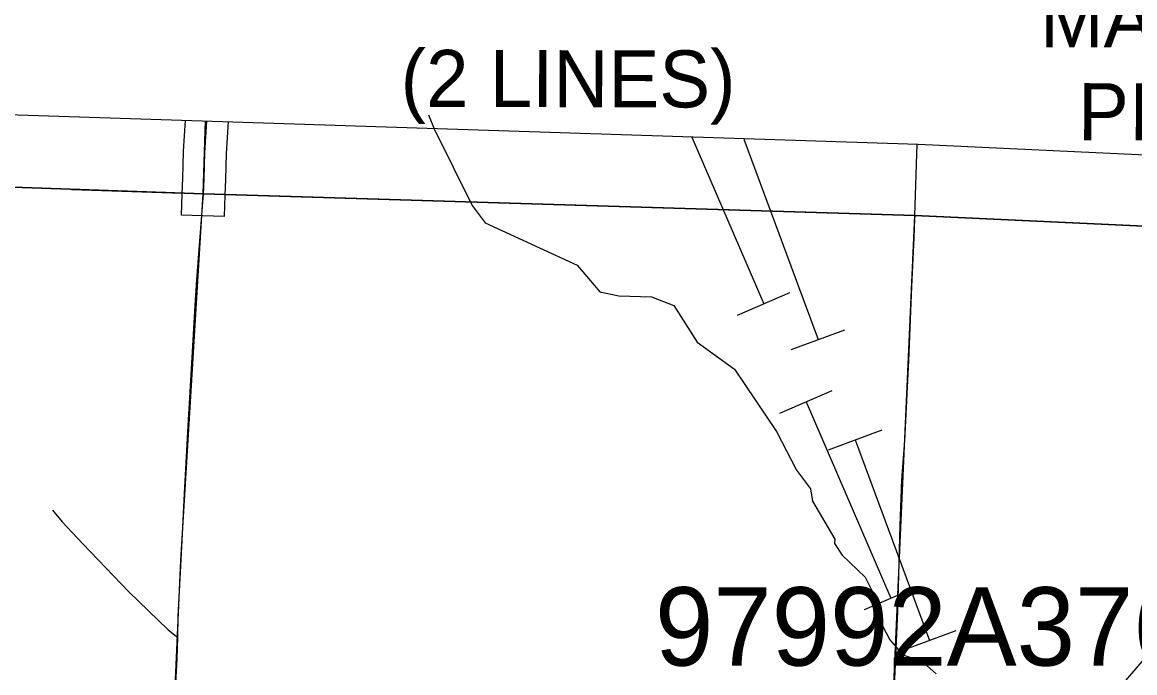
# Model space of a CAD drawing. Extents: x -157.2 to -99.3, y 12.2 to 46.2.
# Drawn here: x -146.67 to -145.11, y 40.555 to 41.468 of the extents above; entities that cross this region are included whole.
import ezdxf

# ---------------------------------------------------------------- set-up
doc = ezdxf.new("R2010")
doc.units = 0
for name, color, linetype in [('tdCoCityStreetMajor', 7, 'Continuous'), ('tdCoCityStreetMinor', 7, 'Continuous'), ('tdCoClipBndry', 7, 'Continuous'), ('tdCoCoBndry', 7, 'Continuous'), ('tdCoCoBndryPart', 7, 'Continuous'), ('tdCoCorpBndry', 7, 'Continuous'), ('tdCoHydroRiver', 7, 'Continuous'), ('tdCoPipe1', 7, 'Continuous'), ('tdCoPipe2', 7, 'Continuous'), ('tdCoPipeTxt', 7, 'Continuous'), ('tdCoSecRteBand', 7, 'Continuous'), ('tdCoSecRteCL', 7, 'Continuous'), ('tdCoSectLine', 7, 'Continuous'), ('tdCoSectLinePart', 7, 'Continuous'), ('tdCoStrucPriMaintName', 7, 'Continuous'), ('tdCoSurfGravel', 7, 'Continuous'), ('tdCoTwpBndryShd', 7, 'Continuous')]:
    doc.layers.add(name, color=color, linetype=linetype)

msp = doc.modelspace()

# ---------------------------------------------------------------- linework, layer by layer
at = {"layer": 'tdCoCityStreetMajor'}
for points in [[(-146.466, 40.2841), (-146.4651, 40.324), (-146.4584, 40.4668), (-146.4548, 40.5322), (-146.4525, 40.5746), (-146.4517, 40.6047), (-146.451, 40.6343), (-146.4453, 40.7499), (-146.4424, 40.8066), (-146.4367, 40.9103), (-146.4355, 40.9332), (-146.4275, 41.0706), (-146.4248, 41.1064), (-146.4169, 41.2096), (-146.4155, 41.2261)], [(-145.1594, 40.4141), (-145.1635, 40.4201), (-145.1769, 40.4397), (-145.1814, 40.4543), (-145.18, 40.4682), (-145.177, 40.4765), (-145.1741, 40.4842), (-145.1691, 40.4902), (-144.9648, 40.7271), (-144.9379, 40.7599), (-144.9254, 40.7728), (-144.8999, 40.7895), (-144.8196, 40.8356), (-144.8009, 40.8468), (-144.7142, 40.9022), (-144.674, 40.9342), (-144.5715, 41.0229), (-144.5405, 41.0492), (-144.5218, 41.0758), (-144.5134, 41.0977), (-144.508, 41.1206), (-144.5065, 41.1489), (-144.5063, 41.1527)]]:
    msp.add_lwpolyline(points, dxfattribs=at)
at = {"layer": 'tdCoCityStreetMinor'}
for points in [[(-145.4192, 41.1653), (-145.418, 41.1916), (-145.4177, 41.1963)], [(-145.4603, 40.2262), (-145.4569, 40.3016), (-145.452, 40.4116), (-145.4476, 40.5174), (-145.4454, 40.5675), (-145.4421, 40.6414), (-145.4387, 40.7618), (-145.4362, 40.8259), (-145.4323, 40.8807), (-145.4264, 40.9929), (-145.4224, 41.0972), (-145.4192, 41.1653)], [(-146.6275, 40.7833), (-146.6139, 40.767), (-146.5848, 40.7362), (-146.5205, 40.6689), (-146.4652, 40.6154), (-146.4517, 40.6047)]]:
    msp.add_lwpolyline(points, dxfattribs=at)
at = {"layer": 'tdCoClipBndry'}
msp.add_lwpolyline([(-150.407, 41.4676), (-149.3946, 41.4438), (-148.3968, 41.411), (-147.4001, 41.3615), (-145.4135, 41.2969), (-142.396, 41.1563), (-141.4008, 41.1294), (-139.4104, 41.0607), (-138.4128, 41.0377), (-137.3849, 40.9986), (-130.3617, 40.7621)], dxfattribs=at)
at = {"layer": 'tdCoCoBndry'}
msp.add_lwpolyline([(-152.9518, 41.3883), (-152.409, 41.3796), (-151.4143, 41.374), (-150.4076, 41.3676), (-149.397, 41.3439), (-148.4001, 41.3111), (-147.4042, 41.2616), (-146.4159, 41.2271), (-145.4182, 41.197), (-144.4306, 41.151), (-143.3778, 41.1032), (-142.3996, 41.0564), (-141.4043, 41.0295), (-140.4086, 40.9954), (-139.4133, 40.9608), (-138.4166, 40.9378), (-137.3885, 40.8986), (-136.3904, 40.8656), (-135.3934, 40.8324), (-134.3958, 40.7988)], dxfattribs=at)
at = {"layer": 'tdCoCoBndryPart'}
for points in [[(-146.6001, 41.2335), (-146.4459, 41.2281)], [(-146.3859, 41.2262), (-145.4182, 41.197), (-144.4439, 41.1516)]]:
    msp.add_lwpolyline(points, dxfattribs=at)
at = {"layer": 'tdCoCorpBndry'}
msp.add_lwpolyline([(-144.5355, 38.1566), (-144.4989, 39.1588), (-144.4828, 39.5029), (-144.4746, 39.5028), (-144.4738, 39.6047), (-144.474, 39.6496), (-144.4741, 39.6804), (-144.4704, 39.7825), (-144.4679, 39.8227), (-144.4618, 39.9381), (-144.4568, 40.0626), (-144.4529, 40.1258), (-144.4527, 40.1488), (-144.4325, 41.0478), (-144.2491, 41.2426), (-144.3711, 41.2483), (-144.3636, 41.2415), (-144.3943, 41.2028), (-144.4298, 41.1658), (-144.4435, 41.1516), (-145.4178, 41.197), (-146.4155, 41.2271), (-147.4038, 41.2616)], dxfattribs=at)
at = {"layer": 'tdCoHydroRiver'}
msp.add_lwpolyline([(-146.1001, 41.3382), (-146.0921, 41.3183), (-146.0389, 41.2108), (-146.0207, 41.1865), (-145.8917, 41.1271), (-145.8598, 41.0897), (-145.8331, 41.0841), (-145.7874, 41.0826), (-145.7562, 41.0706), (-145.7232, 41.019), (-145.6708, 40.981), (-145.6121, 40.8939), (-145.5839, 40.8393), (-145.5643, 40.8134), (-145.5617, 40.796), (-145.5303, 40.7429), (-145.5305, 40.7366), (-145.52, 40.7205), (-145.4879, 40.6894), (-145.4686, 40.6509), (-145.4692, 40.632), (-145.4529, 40.6015), (-145.4347, 40.5804), (-145.4081, 40.5716), (-145.3882, 40.5536)], dxfattribs=at)
at = {"layer": 'tdCoPipe1'}
for p, q in [((-145.5913, 41.0088), (-145.5161, 41.0366)), ((-145.5392, 40.8681), (-145.4641, 40.896)), ((-145.4351, 40.5868), (-145.3599, 40.6146))]:
    msp.add_line(p, q, dxfattribs=at)
for points in [[(-145.6578, 41.3041), (-145.5537, 41.0227)], [(-145.5016, 40.8821), (-145.3975, 40.6007)]]:
    msp.add_lwpolyline(points, dxfattribs=at)
at = {"layer": 'tdCoPipe2'}
for p, q in [((-145.6668, 41.0572), (-145.5932, 41.089)), ((-145.6074, 40.9195), (-145.5338, 40.9512)), ((-145.4885, 40.644), (-145.4149, 40.6758))]:
    msp.add_line(p, q, dxfattribs=at)
for points in [[(-145.7308, 41.3065), (-145.63, 41.0731)], [(-145.5706, 40.9354), (-145.4517, 40.6599)]]:
    msp.add_lwpolyline(points, dxfattribs=at)
at = {"layer": 'tdCoSecRteBand'}
msp.add_lwpolyline([(-146.381, 41.3283), (-146.3838, 41.2837), (-146.3849, 41.2473), (-146.3856, 41.2252), (-146.3865, 41.1952), (-146.4465, 41.1971), (-146.4455, 41.227), (-146.4448, 41.2491), (-146.4437, 41.286), (-146.4437, 41.2864), (-146.4437, 41.2869), (-146.441, 41.3303)], dxfattribs=at)
at = {"layer": 'tdCoSecRteCL'}
msp.add_lwpolyline([(-146.4155, 41.2261), (-146.4149, 41.2482), (-146.4137, 41.285), (-146.411, 41.3293)], dxfattribs=at)
at = {"layer": 'tdCoSectLine'}
for points in [[(-146.4159, 41.2271), (-146.4127, 41.3294)], [(-145.4182, 41.197), (-145.4149, 41.2969)], [(-147.4042, 41.2616), (-146.4159, 41.2271)], [(-146.4664, 40.2841), (-146.4475, 40.7128), (-146.4159, 41.2271)], [(-146.4159, 41.2271), (-145.4182, 41.197)], [(-145.4617, 40.2263), (-145.4182, 41.197)], [(-145.4182, 41.197), (-144.4306, 41.151)]]:
    msp.add_lwpolyline(points, dxfattribs=at)
at = {"layer": 'tdCoSectLinePart'}
for points in [[(-145.4182, 41.197), (-145.4149, 41.2969)], [(-146.6001, 41.2335), (-146.4459, 41.2281)], [(-146.3859, 41.2262), (-145.4182, 41.197)], [(-145.4183, 41.1947), (-145.4182, 41.197)], [(-145.4182, 41.197), (-144.4439, 41.1516)]]:
    msp.add_lwpolyline(points, dxfattribs=at)
at = {"layer": 'tdCoSurfGravel'}
msp.add_lwpolyline([(-146.4155, 41.2261), (-146.4149, 41.2482), (-146.4137, 41.285), (-146.411, 41.3293)], dxfattribs=at)
at = {"layer": 'tdCoTwpBndryShd'}
msp.add_lwpolyline([(-150.4076, 41.3676), (-149.397, 41.3439), (-148.4001, 41.3111), (-147.4042, 41.2616), (-146.4159, 41.2271), (-145.4182, 41.197), (-144.4306, 41.151), (-143.3778, 41.1032), (-142.3996, 41.0564), (-141.4043, 41.0295), (-140.4086, 40.9954), (-139.4133, 40.9608), (-138.4166, 40.9378), (-137.3885, 40.8986), (-136.3904, 40.8656), (-135.3934, 40.8324), (-134.3958, 40.7988)], dxfattribs=at)

# ---------------------------------------------------------------- texts
at = {"layer": 'tdCoPipeTxt'}
for s, p in [('MAGELLAN', (-145.2425, 41.4329)), ('(2 LINES)', (-146.1392, 41.3492)), ('PIPELINE', (-145.1894, 41.3025))]:
    msp.add_text(s, height=0.08, rotation=359.8896, dxfattribs=at).set_placement(p)
at = {"layer": 'tdCoStrucPriMaintName'}
msp.add_text('97992A376', height=0.11, dxfattribs=at).set_placement((-145.7824, 40.5653))

doc.saveas('drawing.dxf')
